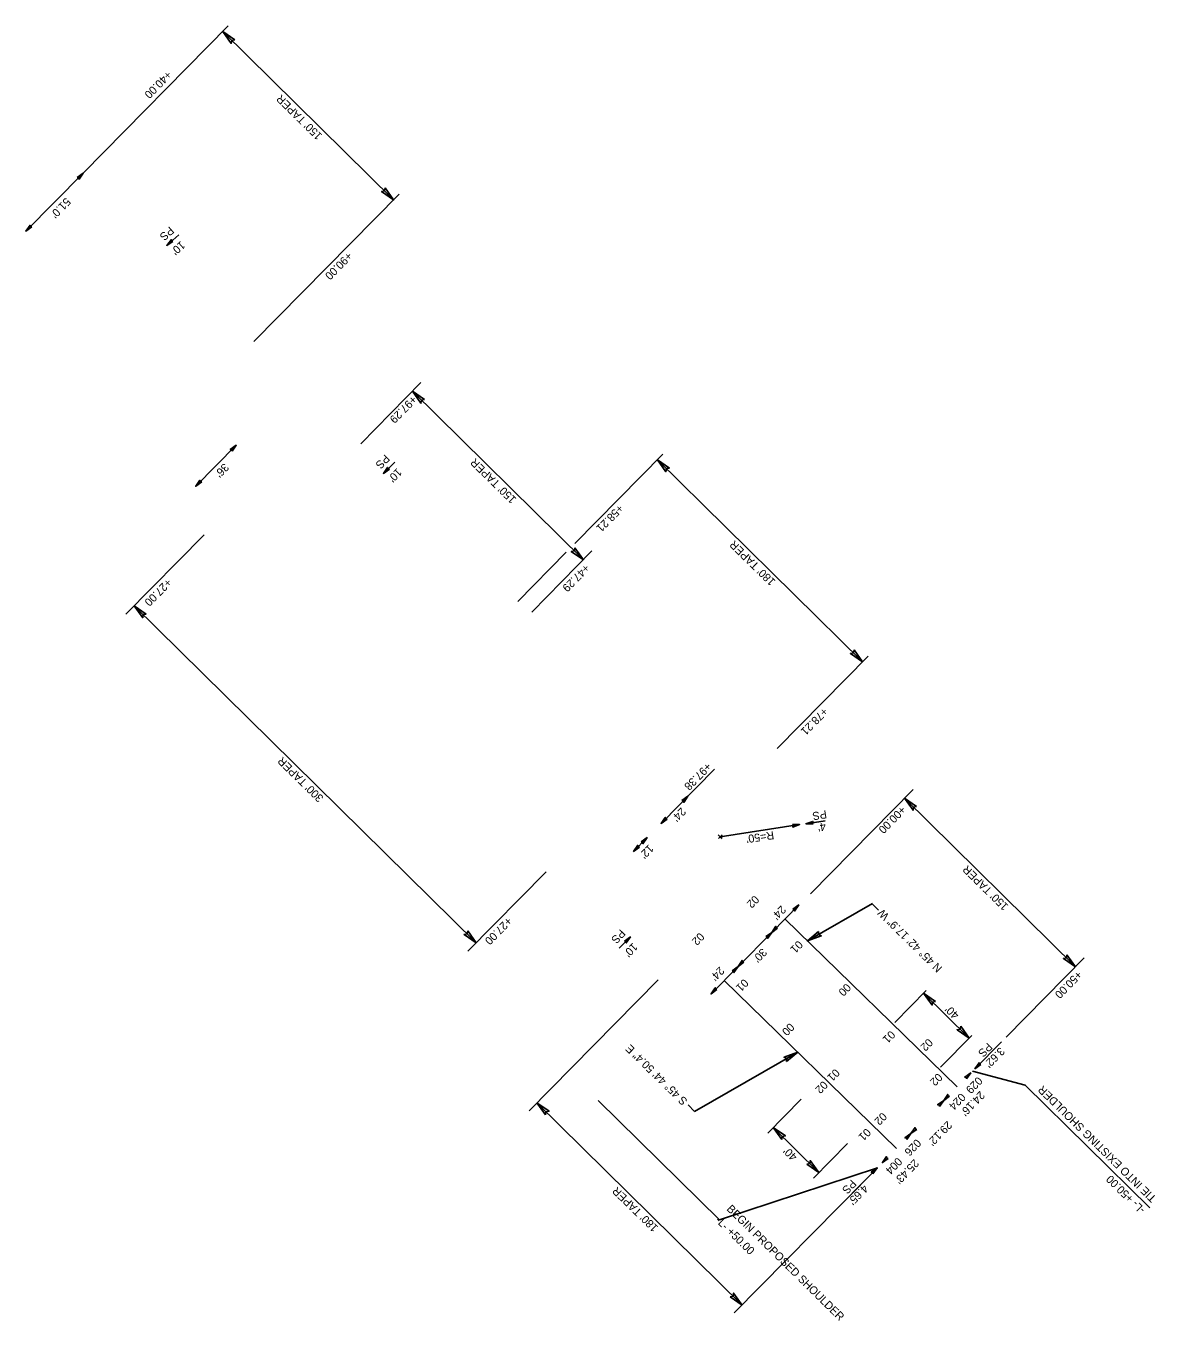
# Model space of a CAD drawing. Extents: x 1262642 to 1268358, y 767825 to 773481.
# Drawn here: x 1264127 to 1264832, y 767825 to 768634 of the extents above; entities that cross this region are included whole.
import ezdxf

# ---------------------------------------------------------------- set-up
doc = ezdxf.new("R2010")
doc.units = 0
for name, color, linetype in [('Prop Dimension', 7, 'Continuous'), ('Prop Dimension Text', 7, 'Continuous'), ('Prop Terminator CELL', 7, 'Continuous')]:
    doc.layers.add(name, color=color, linetype=linetype)

msp = doc.modelspace()

# ---------------------------------------------------------------- linework, layer by layer
at = {"layer": 'Prop Dimension'}
for p, q in [((1264253.23, 768634.3), (1264162.51, 768542.22)), ((1264356.57, 768525.6), (1264249.79, 768630.81)), ((1264162.57, 768542.29), (1264126.78, 768505.96)), ((1264360.01, 768529.09), (1264269.28, 768437.02)), ((1264373.65, 768411.42), (1264335.99, 768373.19)), ((1264475.12, 768300.68), (1264368.27, 768405.96)), ((1264524.83, 768366.69), (1264469.84, 768310.88)), ((1264649.61, 768236.87), (1264521.39, 768363.2)), ((1264238.16, 768316.26), (1264189.27, 768266.64)), ((1264464.39, 768305.36), (1264434.11, 768274.62)), ((1264480.5, 768306.14), (1264442.83, 768267.91)), ((1264408.18, 768061.35), (1264194.47, 768271.92)), ((1264653.05, 768240.36), (1264596.21, 768182.67)), ((1264681.2, 768157.08), (1264617.04, 768091.97)), ((1264782.67, 768046.34), (1264675.82, 768151.62)), ((1264614.24, 768135.71), (1264626.17, 768137.53)), ((1264560.68, 768127.58), (1264559.46, 768128.78)), ((1264560.68, 768127.58), (1264559.48, 768126.37)), ((1264560.68, 768127.58), (1264610.29, 768135.11)), ((1264561.88, 768128.8), (1264560.68, 768127.58)), ((1264561.89, 768126.38), (1264560.68, 768127.58)), ((1264451.87, 768105.69), (1264402.98, 768056.07)), ((1264655.75, 768085.76), (1264615.12, 768062.48)), ((1264659.66, 768081.59), (1264655.59, 768085.6)), ((1264788.04, 768051.8), (1264739.29, 768002.32)), ((1264521.97, 768038.22), (1264441.23, 767956.28)), ((1264689.37, 768031.43), (1264669.78, 768011.56)), ((1264716.26, 768001.75), (1264687.78, 768029.82)), ((1264717.86, 768003.36), (1264698.27, 767983.49)), ((1264544.64, 767955.9), (1264609.16, 767992.87)), ((1264574.32, 767834.89), (1264446.1, 767961.23)), ((1264540.57, 767959.91), (1264544.64, 767955.9)), ((1264590.39, 767942.35), (1264611.33, 767963.6)), ((1264622.28, 767917.72), (1264593.79, 767945.79)), ((1264618.88, 767914.28), (1264640.18, 767935.89)), ((1264651.24, 767912.96), (1264569.45, 767829.95))]:
    msp.add_line(p, q, dxfattribs=at)
for points in [[(1264130.47, 768508.64), (1264126.78, 768505.96), (1264129.36, 768509.76), (1264129.54, 768508.79)], [(1264218.69, 768499.5), (1264214.79, 768497.13), (1264217.67, 768500.71), (1264217.76, 768499.73)], [(1264255.6, 768368.49), (1264258.23, 768372.23), (1264254.47, 768369.58), (1264255.44, 768369.43)], [(1264353.91, 768357.27), (1264350.21, 768354.6), (1264352.8, 768358.39), (1264352.97, 768357.42)], [(1264236.66, 768349.26), (1264232.96, 768346.58), (1264235.55, 768350.38), (1264235.72, 768349.41)], [(1264527.43, 768138.57), (1264523.74, 768135.89), (1264526.32, 768139.68), (1264526.5, 768138.71)], [(1264510.24, 768121.11), (1264506.55, 768118.43), (1264509.13, 768122.23), (1264509.31, 768121.26)], [(1264596.53, 768070.49), (1264592.83, 768067.81), (1264595.42, 768071.6), (1264595.59, 768070.63)], [(1264575.47, 768049.12), (1264571.78, 768046.44), (1264574.36, 768050.23), (1264574.53, 768049.26)], [(1264558.63, 768032.02), (1264554.93, 768029.34), (1264557.52, 768033.14), (1264557.69, 768032.17)]]:
    msp.add_lwpolyline(points, close=True, dxfattribs=at)
at = {"layer": 'Prop Dimension Text'}
for p, q in [((1264214.79, 768497.13), (1264222.35, 768503.67)), ((1264258.23, 768372.23), (1264232.96, 768346.58)), ((1264350.21, 768354.6), (1264357.23, 768361.72)), ((1264523.74, 768135.89), (1264557.12, 768169.76)), ((1264506.55, 768118.43), (1264514.97, 768126.98)), ((1264592.83, 768067.81), (1264609.68, 768084.9)), ((1264708.62, 767971.26), (1264601.08, 768076.18)), ((1264497.51, 768057.85), (1264504.53, 768064.97)), ((1264571.78, 768046.44), (1264592.83, 768067.81)), ((1264554.93, 768029.34), (1264571.78, 768046.44)), ((1264563.16, 768037.69), (1264670.8, 767932.81)), ((1264736.49, 767999.48), (1264719.79, 767982.53)), ((1264829.03, 767895.62), (1264751.11, 767972.4)), ((1264484.33, 767962.72), (1264560.11, 767888.04)), ((1264637.94, 767899.46), (1264658.91, 767920.74))]:
    msp.add_line(p, q, dxfattribs=at)
for points in [[(1264257.29, 768625.6), (1264249.79, 768630.81), (1264255.12, 768623.32), (1264255.42, 768625.26)], [(1264158.87, 768539.61), (1264162.57, 768542.29), (1264159.98, 768538.49), (1264159.81, 768539.46)], [(1264351.25, 768533.02), (1264356.57, 768525.6), (1264349, 768530.81), (1264350.94, 768531.15)], [(1264375.77, 768400.74), (1264368.27, 768405.96), (1264373.6, 768398.47), (1264373.9, 768400.41)], [(1264528.89, 768357.99), (1264521.39, 768363.2), (1264526.71, 768355.71), (1264527.02, 768357.66)], [(1264469.8, 768308.1), (1264475.12, 768300.68), (1264467.55, 768305.89), (1264469.49, 768306.22)], [(1264201.97, 768266.71), (1264194.47, 768271.92), (1264199.8, 768264.43), (1264200.1, 768266.38)], [(1264644.28, 768244.29), (1264649.61, 768236.87), (1264642.04, 768242.08), (1264643.98, 768242.41)], [(1264536.73, 768150.15), (1264540.43, 768152.83), (1264537.84, 768149.03), (1264537.67, 768150)], [(1264683.32, 768146.41), (1264675.82, 768151.62), (1264681.14, 768144.13), (1264681.45, 768146.08)], [(1264511.27, 768124.3), (1264514.97, 768126.98), (1264512.38, 768123.18), (1264512.21, 768124.15)], [(1264605.98, 768082.22), (1264609.68, 768084.9), (1264607.09, 768081.11), (1264606.92, 768082.08)], [(1264402.86, 768068.77), (1264408.18, 768061.35), (1264400.61, 768066.56), (1264402.55, 768066.9)], [(1264500.83, 768062.29), (1264504.53, 768064.97), (1264501.94, 768061.17), (1264501.77, 768062.14)], [(1264589.13, 768065.13), (1264592.83, 768067.81), (1264590.24, 768064.01), (1264590.07, 768064.98)], [(1264622.16, 768068.3), (1264615.12, 768062.48), (1264623.77, 768065.59), (1264621.97, 768066.41)], [(1264568.08, 768043.76), (1264571.78, 768046.44), (1264569.19, 768042.64), (1264569.02, 768043.61)], [(1264777.34, 768053.76), (1264782.67, 768046.34), (1264775.1, 768051.56), (1264777.04, 768051.89)], [(1264695.27, 768024.61), (1264687.78, 768029.82), (1264693.1, 768022.33), (1264693.4, 768024.27)], [(1264710.94, 768009.17), (1264716.26, 768001.75), (1264708.69, 768006.96), (1264710.64, 768007.29)], [(1264602.12, 767987.05), (1264609.16, 767992.87), (1264600.51, 767989.76), (1264602.31, 767988.94)], [(1264723.49, 767985.21), (1264719.79, 767982.53), (1264722.38, 767986.33), (1264722.55, 767985.36)], [(1264714.62, 767976.21), (1264717.25, 767979.95), (1264713.49, 767977.31), (1264714.46, 767977.15)], [(1264703.99, 767965.42), (1264700.29, 767962.74), (1264702.88, 767966.54), (1264703.05, 767965.57)], [(1264451.43, 767953.8), (1264446.1, 767961.22), (1264453.67, 767956.01), (1264451.73, 767955.68)], [(1264697.67, 767959), (1264700.29, 767962.74), (1264696.53, 767960.1), (1264697.5, 767959.94)], [(1264599.11, 767938.37), (1264593.79, 767945.79), (1264601.36, 767940.58), (1264599.42, 767940.25)], [(1264677.23, 767938.26), (1264679.85, 767941.99), (1264676.09, 767939.35), (1264677.06, 767939.19)], [(1264683.55, 767944.67), (1264679.85, 767941.99), (1264682.44, 767945.79), (1264682.61, 767944.82)], [(1264614.78, 767922.94), (1264622.28, 767917.72), (1264616.95, 767925.21), (1264616.65, 767923.27)], [(1264665.7, 767926.56), (1264662, 767923.88), (1264664.59, 767927.68), (1264664.76, 767926.71)], [(1264656.11, 767916.83), (1264658.74, 767920.57), (1264654.98, 767917.92), (1264655.95, 767917.77)], [(1264566.82, 767840.1), (1264574.32, 767834.89), (1264569, 767842.38), (1264568.69, 767840.44)]]:
    msp.add_lwpolyline(points, close=True, dxfattribs=at)
for points in [[(1264751.11, 767972.4), (1264718.36, 767981.08)], [(1264560.11, 767888.04), (1264658.88, 767920.73)]]:
    msp.add_lwpolyline(points, dxfattribs=at)
at = {"layer": 'Prop Terminator CELL'}
for points in [[(1264618.81, 768135.62), (1264614.24, 768135.71), (1264618.59, 768137.18), (1264618.15, 768136.31)], [(1264605.72, 768135.2), (1264610.29, 768135.11), (1264605.93, 768133.64), (1264606.38, 768134.52)]]:
    msp.add_lwpolyline(points, close=True, dxfattribs=at)

# ---------------------------------------------------------------- texts
at = {"layer": 'Prop Dimension Text'}
for s, rotation, p in [('+40.00', 225.42387, (1264214.95, 768606.61)), ("150' TAPER", 135.42387, (1264312.32, 768565.99)), ("51.0'", 225.69483, (1264151.77, 768527.34)), ('PS', 221.12091, (1264216.62, 768509.27)), ("10'", 221.12091, (1264223.63, 768500.15)), ('+90.00', 225.42387, (1264327.79, 768493.31)), ('+97.29', 225.42387, (1264368.15, 768403.66)), ('PS', 225.69483, (1264351.08, 768366.84)), ("150' TAPER", 135.42387, (1264433.57, 768338.77)), ("36'", 225.69483, (1264250.6, 768361.32)), ("10'", 225.69483, (1264358.78, 768358.31)), ('+58.21', 225.42387, (1264497.26, 768335.66)), ("180' TAPER", 135.42387, (1264595.5, 768287.42)), ('+47.29', 225.42387, (1264476.09, 768298.3)), ('+27.00', 225.42387, (1264214.95, 768289.34)), ('+78.21', 225.42387, (1264625.03, 768208.69)), ("300' TAPER", 135.42387, (1264313.09, 768152.18)), ('+97.38', 225.42387, (1264552.21, 768174.26)), ("24'", 225.69483, (1264536.23, 768146.18)), ('PS', 188.63181, (1264626.82, 768144.13)), ('+00.00', 225.42387, (1264673.65, 768147.24)), ("4'", 188.63181, (1264626.24, 768136.45)), ("R=50'", 188.63181, (1264593.86, 768131.08)), ("12'", 225.69483, (1264516.04, 768123.08)), ("150' TAPER", 135.42387, (1264741.11, 768084.44)), ('02', 225.69483, (1264581.98, 768091.25)), ("24'", 225.69483, (1264598.72, 768084.9)), ('N 45%%d 42\' 17.9" W', 135.52635, (1264699.74, 768045.81)), ('+27.00', 225.42387, (1264427.63, 768077.73)), ('PS', 225.69483, (1264498.37, 768070.09)), ('02', 225.69483, (1264547.74, 768068.01)), ('01', 225.69483, (1264609.26, 768063.06)), ("10'", 225.69483, (1264506.08, 768061.56)), ("30'", 225.69483, (1264586.82, 768058.23)), ("24'", 225.69483, (1264560.24, 768046.71)), ('01', 225.69483, (1264575.29, 768039.12)), ('+50.00', 225.42387, (1264783.83, 768044.16)), ('00', 225.69483, (1264639.33, 768036.26)), ("40'", 135.45779, (1264710.3, 768016.52)), ('00', 225.69483, (1264603.98, 768011.52)), ('01', 225.69483, (1264667.01, 768006.75)), ('S 45%%d 44\' 50.4" E', 135.56873, (1264540.56, 767962.75)), ('02', 225.69483, (1264690.51, 768001.86)), ('PS', 225.15291, (1264727.72, 767999.21)), ("3.62'", 225.15291, (1264735.48, 767996.37)), ('01', 225.69483, (1264632.33, 767982.92)), ('02', 225.69483, (1264624.84, 767975.33)), ('02', 225.69483, (1264696.51, 767980.15)), ('029', 225.69483, (1264721.55, 767977.97)), ('024', 225.69483, (1264710.98, 767967.73)), ("24.16'", 225.69483, (1264723, 767968.92)), ('TIE INTO EXISTING SHOULDER', 135.42387, (1264833.63, 767902.09)), ('02', 225.69483, (1264661.8, 767955.62)), ("29.12'", 225.69483, (1264702.54, 767950.28)), ('01', 225.69483, (1264651.81, 767945.7)), ('026', 225.69483, (1264683.18, 767939.03)), ("40'", 135.42387, (1264609.22, 767927.95)), ('004', 225.69483, (1264671.34, 767927.5)), ("25.43'", 225.69483, (1264681.81, 767926.41)), ("180' TAPER", 135.56873, (1264522.27, 767883.57)), ('PS', 225.15291, (1264642.73, 767913.65)), ("4.65'", 225.15291, (1264650.24, 767910.57)), ('-L- +50.00', 135.42387, (1264826.61, 767894.96)), ('BEGIN PROPOSED SHOULDER', 315.42387, (1264564.3, 767894.52)), ('-L- +50.00', 315.42387, (1264557.28, 767887.4))]:
    msp.add_text(s, height=5, rotation=rotation, dxfattribs=at).set_placement(p)

doc.saveas('drawing.dxf')
